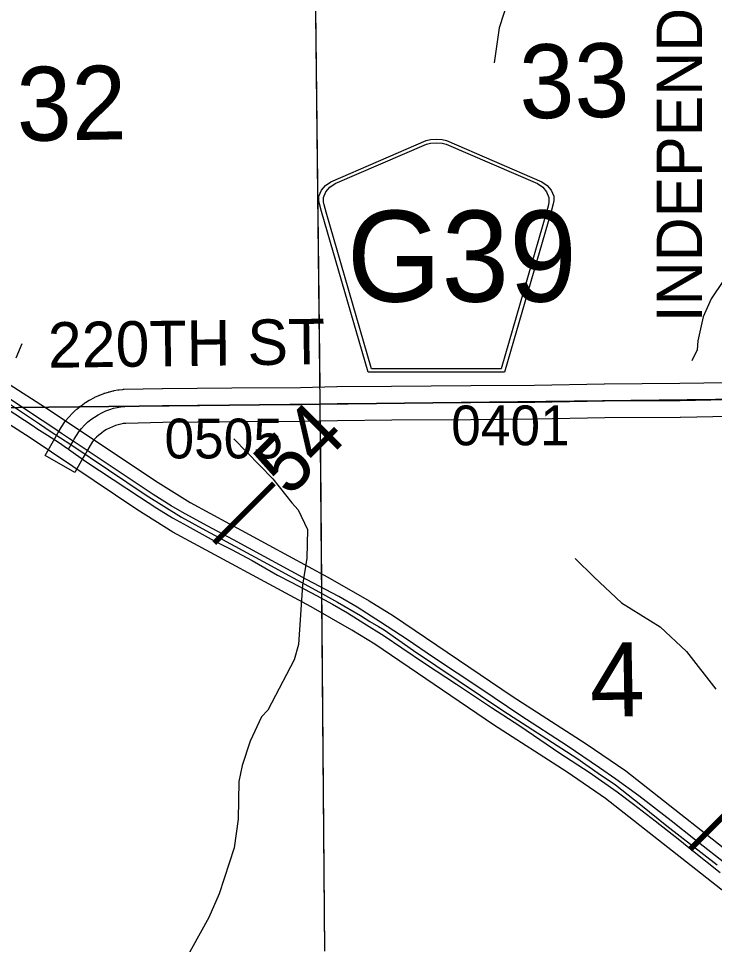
# Model space of a CAD drawing. Extents: x 23.6 to 68.7, y -63 to -29.
# Drawn here: x 40.131 to 41.355, y -46.611 to -44.982 of the extents above; entities that cross this region are included whole.
import ezdxf

# ---------------------------------------------------------------- set-up
doc = ezdxf.new("R2010")
doc.units = 0
for name, color, linetype in [('tdCoDivCarto', 7, 'Continuous'), ('tdCoHydroRiver', 7, 'Continuous'), ('tdCoPriCL', 7, 'Continuous'), ('tdCoPriDiv', 7, 'Continuous'), ('tdCoPrimary', 7, 'Continuous'), ('tdCoSecRdNmbr', 7, 'Continuous'), ('tdCoSecRdTxt', 7, 'Continuous'), ('tdCoSecRteBand', 7, 'Continuous'), ('tdCoSecRteCL', 7, 'Continuous'), ('tdCoSectLine', 7, 'Continuous'), ('tdCoSectLinePart', 7, 'Continuous'), ('tdCoSectNmbr', 7, 'Continuous'), ('tdCoShieldCoRte', 7, 'Continuous'), ('tdCoSurfGravel', 7, 'Continuous'), ('tdCoTwpBndryShd', 7, 'Continuous'), ('tdStHwyPriRefPost1', 7, 'Continuous'), ('tdStHwyPriRefPost5', 7, 'Continuous')]:
    doc.layers.add(name, color=color, linetype=linetype)

msp = doc.modelspace()

# ---------------------------------------------------------------- linework, layer by layer
at = {"layer": 'tdCoDivCarto'}
for p, q in [((40.1725, -45.6894), (40.1031, -45.643)), ((40.1096, -45.6677), (40.1569, -45.699)), ((40.1911, -45.7019), (40.1725, -45.6894)), ((40.1911, -45.7019), (40.1725, -45.6894)), ((40.1569, -45.699), (40.1635, -45.7032)), ((40.1635, -45.7032), (40.1823, -45.7154)), ((40.1635, -45.7032), (40.1823, -45.7154)), ((40.2064, -45.7121), (40.1911, -45.7019)), ((40.2208, -45.7216), (40.2064, -45.7121)), ((40.1823, -45.7154), (40.2013, -45.7276)), ((40.2013, -45.7276), (40.2169, -45.7385)), ((40.2269, -45.7256), (40.2208, -45.7216)), ((40.2273, -45.7259), (40.2269, -45.7256)), ((40.271, -45.7552), (40.2273, -45.7259)), ((40.2169, -45.7385), (40.2181, -45.7393)), ((40.2181, -45.7393), (40.2188, -45.7398)), ((40.2188, -45.7398), (40.2496, -45.7614)), ((40.2496, -45.7614), (40.2977, -45.7929)), ((40.329, -45.7939), (40.271, -45.7552)), ((40.2977, -45.7929), (40.3436, -45.8238)), ((40.3677, -45.8196), (40.329, -45.7939)), ((40.3436, -45.8238), (40.3744, -45.8435)), ((40.3995, -45.8393), (40.3677, -45.8196)), ((40.3744, -45.8435), (40.4018, -45.8608)), ((40.4187, -45.8507), (40.3995, -45.8393)), ((40.4018, -45.8608), (40.4277, -45.8748)), ((40.4626, -45.8746), (40.4187, -45.8507)), ((40.4277, -45.8748), (40.4753, -45.9007)), ((40.509, -45.899), (40.4626, -45.8746)), ((40.4753, -45.9007), (40.5056, -45.916)), ((40.5627, -45.9283), (40.509, -45.899)), ((40.5056, -45.916), (40.5419, -45.9355)), ((40.5419, -45.9355), (40.5865, -45.9611)), ((40.6375, -45.969), (40.5627, -45.9283)), ((40.5865, -45.9611), (40.6116, -45.9744)), ((40.6116, -45.9744), (40.655, -45.9974)), ((40.6944, -45.9991), (40.6375, -45.969)), ((40.655, -45.9974), (40.6832, -46.0124)), ((40.7262, -46.0176), (40.6944, -45.9991)), ((40.6832, -46.0124), (40.7095, -46.0277)), ((40.7672, -46.044), (40.7262, -46.0176)), ((40.7095, -46.0277), (40.7384, -46.0457)), ((40.7384, -46.0457), (40.7739, -46.0681)), ((40.8145, -46.0748), (40.7672, -46.044)), ((40.7739, -46.0681), (40.805, -46.0889)), ((40.805, -46.0889), (40.8464, -46.1175)), ((40.8609, -46.1064), (40.8145, -46.0748)), ((40.8464, -46.1175), (40.9012, -46.1532)), ((40.944, -46.1614), (40.8609, -46.1064)), ((40.9012, -46.1532), (40.9362, -46.1767)), ((41.0143, -46.2087), (40.944, -46.1614)), ((40.9362, -46.1767), (40.9623, -46.1939)), ((40.9623, -46.1939), (41.0124, -46.2262)), ((41.0954, -46.2617), (41.0143, -46.2087)), ((41.0124, -46.2262), (41.0829, -46.2743)), ((41.1524, -46.3005), (41.0954, -46.2617)), ((41.0829, -46.2743), (41.1342, -46.3079)), ((41.1812, -46.3204), (41.1524, -46.3005)), ((41.1342, -46.3079), (41.1835, -46.3426)), ((41.2217, -46.3495), (41.1812, -46.3204)), ((41.1835, -46.3426), (41.2124, -46.3641)), ((41.2786, -46.3937), (41.2217, -46.3495)), ((41.2124, -46.3641), (41.2501, -46.3932)), ((41.2501, -46.3932), (41.2938, -46.4277)), ((41.3213, -46.4277), (41.2786, -46.3937)), ((41.2938, -46.4277), (41.3162, -46.4457)), ((41.3783, -46.4721), (41.3213, -46.4277)), ((41.3162, -46.4457), (41.3645, -46.4842))]:
    msp.add_line(p, q, dxfattribs=at)
for points in [[(40.1725, -45.6894), (40.1031, -45.643), (40.0974, -45.6391)], [(40.1725, -45.6894), (40.1031, -45.643), (40.0974, -45.6391)], [(40.1725, -45.6894), (40.1031, -45.643), (40.0974, -45.6391)], [(40.0878, -45.6534), (40.1096, -45.6677), (40.1569, -45.699), (40.1635, -45.7032)], [(40.0878, -45.6534), (40.1096, -45.6677), (40.1569, -45.699), (40.1635, -45.7032)], [(40.0878, -45.6534), (40.1096, -45.6677), (40.1569, -45.699), (40.1635, -45.7032)], [(40.1911, -45.7019), (40.1725, -45.6894)], [(40.1911, -45.7019), (40.1725, -45.6894)], [(40.1635, -45.7032), (40.1823, -45.7154)], [(40.1635, -45.7032), (40.1823, -45.7154)], [(40.2273, -45.7259), (40.2269, -45.7256), (40.2208, -45.7216), (40.2064, -45.7121), (40.1911, -45.7019)], [(40.2273, -45.7259), (40.2269, -45.7256), (40.2208, -45.7216), (40.2064, -45.7121), (40.1911, -45.7019)], [(40.2273, -45.7259), (40.2269, -45.7256), (40.2208, -45.7216), (40.2064, -45.7121), (40.1911, -45.7019)], [(40.1823, -45.7154), (40.2013, -45.7276), (40.2169, -45.7385), (40.2181, -45.7393)], [(40.1823, -45.7154), (40.2013, -45.7276), (40.2169, -45.7385), (40.2181, -45.7393)], [(40.1823, -45.7154), (40.2013, -45.7276), (40.2169, -45.7385), (40.2181, -45.7393)], [(41.3783, -46.4721), (41.3213, -46.4277), (41.2786, -46.3937), (41.2217, -46.3495), (41.1812, -46.3204), (41.1524, -46.3005), (41.0954, -46.2617), (41.0143, -46.2087), (40.944, -46.1614), (40.8609, -46.1064), (40.8145, -46.0748), (40.7672, -46.044), (40.7262, -46.0176), (40.6944, -45.9991), (40.6375, -45.969), (40.5627, -45.9283), (40.509, -45.899), (40.4626, -45.8746), (40.4187, -45.8507), (40.3995, -45.8393), (40.3677, -45.8196), (40.329, -45.7939), (40.271, -45.7552), (40.2273, -45.7259)], [(41.3783, -46.4721), (41.3213, -46.4277), (41.2786, -46.3937), (41.2217, -46.3495), (41.1812, -46.3204), (41.1524, -46.3005), (41.0954, -46.2617), (41.0143, -46.2087), (40.944, -46.1614), (40.8609, -46.1064), (40.8145, -46.0748), (40.7672, -46.044), (40.7262, -46.0176), (40.6944, -45.9991), (40.6375, -45.969), (40.5627, -45.9283), (40.509, -45.899), (40.4626, -45.8746), (40.4187, -45.8507), (40.3995, -45.8393), (40.3677, -45.8196), (40.329, -45.7939), (40.271, -45.7552), (40.2273, -45.7259)], [(41.3783, -46.4721), (41.3213, -46.4277), (41.2786, -46.3937), (41.2217, -46.3495), (41.1812, -46.3204), (41.1524, -46.3005), (41.0954, -46.2617), (41.0143, -46.2087), (40.944, -46.1614), (40.8609, -46.1064), (40.8145, -46.0748), (40.7672, -46.044), (40.7262, -46.0176), (40.6944, -45.9991), (40.6375, -45.969), (40.5627, -45.9283), (40.509, -45.899), (40.4626, -45.8746), (40.4187, -45.8507), (40.3995, -45.8393), (40.3677, -45.8196), (40.329, -45.7939), (40.271, -45.7552), (40.2273, -45.7259)], [(40.2181, -45.7393), (40.2188, -45.7398), (40.2496, -45.7614), (40.2977, -45.7929), (40.3436, -45.8238), (40.3744, -45.8435), (40.4018, -45.8608), (40.4277, -45.8748), (40.4753, -45.9007), (40.5056, -45.916), (40.5419, -45.9355), (40.5865, -45.9611), (40.6116, -45.9744), (40.655, -45.9974), (40.6832, -46.0124), (40.7095, -46.0277), (40.7384, -46.0457), (40.7739, -46.0681), (40.805, -46.0889), (40.8464, -46.1175), (40.9012, -46.1532), (40.9362, -46.1767), (40.9623, -46.1939), (41.0124, -46.2262), (41.0829, -46.2743), (41.1342, -46.3079), (41.1835, -46.3426), (41.2124, -46.3641), (41.2501, -46.3932), (41.2938, -46.4277), (41.3162, -46.4457), (41.3645, -46.4842)], [(40.2181, -45.7393), (40.2188, -45.7398), (40.2496, -45.7614), (40.2977, -45.7929), (40.3436, -45.8238), (40.3744, -45.8435), (40.4018, -45.8608), (40.4277, -45.8748), (40.4753, -45.9007), (40.5056, -45.916), (40.5419, -45.9355), (40.5865, -45.9611), (40.6116, -45.9744), (40.655, -45.9974), (40.6832, -46.0124), (40.7095, -46.0277), (40.7384, -46.0457), (40.7739, -46.0681), (40.805, -46.0889), (40.8464, -46.1175), (40.9012, -46.1532), (40.9362, -46.1767), (40.9623, -46.1939), (41.0124, -46.2262), (41.0829, -46.2743), (41.1342, -46.3079), (41.1835, -46.3426), (41.2124, -46.3641), (41.2501, -46.3932), (41.2938, -46.4277), (41.3162, -46.4457), (41.3645, -46.4842)], [(40.2181, -45.7393), (40.2188, -45.7398), (40.2496, -45.7614), (40.2977, -45.7929), (40.3436, -45.8238), (40.3744, -45.8435), (40.4018, -45.8608), (40.4277, -45.8748), (40.4753, -45.9007), (40.5056, -45.916), (40.5419, -45.9355), (40.5865, -45.9611), (40.6116, -45.9744), (40.655, -45.9974), (40.6832, -46.0124), (40.7095, -46.0277), (40.7384, -46.0457), (40.7739, -46.0681), (40.805, -46.0889), (40.8464, -46.1175), (40.9012, -46.1532), (40.9362, -46.1767), (40.9623, -46.1939), (41.0124, -46.2262), (41.0829, -46.2743), (41.1342, -46.3079), (41.1835, -46.3426), (41.2124, -46.3641), (41.2501, -46.3932), (41.2938, -46.4277), (41.3162, -46.4457), (41.3645, -46.4842)]]:
    msp.add_lwpolyline(points, dxfattribs=at)
at = {"layer": 'tdCoHydroRiver'}
for points in [[(41.3635, -44.5499), (41.3511, -44.5769), (41.3371, -44.5928), (41.3309, -44.6055), (41.2807, -44.6438), (41.2072, -44.7156), (41.0929, -44.8114), (41.0397, -44.8671), (41.0195, -44.8942), (40.9916, -44.9497), (40.9763, -44.9987), (40.9674, -45.0604)], [(41.3704, -45.4433), (41.3486, -45.4751), (41.3347, -45.5068), (41.3256, -45.5495), (41.3242, -45.5653), (41.3149, -45.5843)], [(40.137, -45.5545), (40.1262, -45.5798)], [(40.5096, -45.7214), (40.5781, -45.7918), (40.6117, -45.8341), (40.6228, -45.8466), (40.6389, -45.8812), (40.6378, -45.9317), (40.6304, -45.9791), (40.6235, -46.0834), (40.6158, -46.1103), (40.5693, -46.1991), (40.5584, -46.2103), (40.5383, -46.2531), (40.5245, -46.2959), (40.5184, -46.3243), (40.5175, -46.3906), (40.5101, -46.4412), (40.484, -46.522), (40.4654, -46.5632), (40.4018, -46.679)], [(41.1098, -45.932), (41.1433, -45.9648), (41.1911, -46.0101), (41.2593, -46.0521), (41.3055, -46.0959), (41.3567, -46.1617)]]:
    msp.add_lwpolyline(points, dxfattribs=at)
at = {"layer": 'tdCoPriCL'}
msp.add_lwpolyline([(40.1172, -45.6613), (40.1682, -45.6953), (40.1866, -45.7082), (40.223, -45.7318), (40.3556, -45.8208), (40.4176, -45.8596), (40.4542, -45.8793), (40.5611, -45.9374), (40.6603, -45.991), (40.6917, -46.0087), (40.7323, -46.0324), (40.7486, -46.0426), (40.7639, -46.0516), (40.774, -46.0578), (40.8253, -46.0939), (40.9826, -46.1994), (41.1125, -46.2831), (41.1503, -46.3096), (41.1807, -46.3299), (41.2252, -46.3655), (41.2709, -46.4021), (41.3594, -46.4707)], dxfattribs=at)
at = {"layer": 'tdCoPriDiv'}
for points in [[(41.3902, -46.5327), (41.163, -46.3542), (41.0958, -46.308), (40.9662, -46.2244), (40.7576, -46.0829), (40.7169, -46.0581), (40.6458, -46.0172), (40.4026, -45.8856), (40.3393, -45.846), (40.1513, -45.7201), (40.0759, -45.672), (40.0211, -45.6356), (39.9494, -45.5847), (39.7956, -45.4821), (39.6357, -45.3738), (39.039, -44.9752), (38.811, -44.8202), (38.7533, -44.7818), (38.6853, -44.7238), (38.6486, -44.6876), (38.6183, -44.6558), (38.5702, -44.6089), (38.5405, -44.5829), (38.379, -44.4338)], [(39.0725, -44.9254), (39.6693, -45.3242), (39.8281, -45.4316), (39.9836, -45.5354), (40.0549, -45.586), (40.1079, -45.6213), (40.1852, -45.6705), (40.3719, -45.7956), (40.4328, -45.8336), (40.6749, -45.9647), (40.7478, -46.0067), (40.7905, -46.0327), (40.9991, -46.1743), (41.1293, -46.2582), (41.1985, -46.3057), (41.4276, -46.4858)]]:
    msp.add_lwpolyline(points, dxfattribs=at)
at = {"layer": 'tdCoPrimary'}
for p, q in [((40.1911, -45.7019), (40.1725, -45.6894)), ((40.1911, -45.7019), (40.1725, -45.6894)), ((40.1635, -45.7032), (40.1823, -45.7154)), ((40.1635, -45.7032), (40.1823, -45.7154))]:
    msp.add_line(p, q, dxfattribs=at)
for points in [[(40.1725, -45.6894), (40.1031, -45.643), (40.0974, -45.6391)], [(40.1725, -45.6894), (40.1031, -45.643), (40.0974, -45.6391)], [(41.3783, -46.4721), (41.3213, -46.4277), (41.2786, -46.3937), (41.2217, -46.3495), (41.1812, -46.3204), (41.1524, -46.3005), (41.0954, -46.2617), (41.0143, -46.2087), (40.944, -46.1614), (40.8609, -46.1064), (40.8145, -46.0748), (40.7672, -46.044), (40.7262, -46.0176), (40.6944, -45.9991), (40.6375, -45.969), (40.5627, -45.9283), (40.509, -45.899), (40.4626, -45.8746), (40.4187, -45.8507), (40.3995, -45.8393), (40.3677, -45.8196), (40.329, -45.7939), (40.271, -45.7552), (40.2273, -45.7259), (40.2269, -45.7256), (40.2208, -45.7216), (40.2064, -45.7121), (40.1911, -45.7019), (40.1725, -45.6894), (40.1031, -45.643)], [(40.0878, -45.6534), (40.1096, -45.6677), (40.1569, -45.699), (40.1635, -45.7032)], [(40.0878, -45.6534), (40.1096, -45.6677), (40.1569, -45.699), (40.1635, -45.7032)], [(40.1096, -45.6677), (40.1569, -45.699), (40.1635, -45.7032), (40.1823, -45.7154), (40.2013, -45.7276), (40.2169, -45.7385), (40.2181, -45.7393), (40.2188, -45.7398), (40.2496, -45.7614), (40.2977, -45.7929), (40.3436, -45.8238), (40.3744, -45.8435), (40.4018, -45.8608), (40.4277, -45.8748), (40.4753, -45.9007), (40.5056, -45.916), (40.5419, -45.9355), (40.5865, -45.9611), (40.6116, -45.9744), (40.655, -45.9974), (40.6832, -46.0124), (40.7095, -46.0277), (40.7384, -46.0457), (40.7739, -46.0681), (40.805, -46.0889), (40.8464, -46.1175), (40.9012, -46.1532), (40.9362, -46.1767), (40.9623, -46.1939), (41.0124, -46.2262), (41.0829, -46.2743), (41.1342, -46.3079), (41.1835, -46.3426), (41.2124, -46.3641), (41.2501, -46.3932), (41.2938, -46.4277), (41.3162, -46.4457), (41.3645, -46.4842)], [(40.2273, -45.7259), (40.2269, -45.7256), (40.2208, -45.7216), (40.2064, -45.7121), (40.1911, -45.7019)], [(40.2273, -45.7259), (40.2269, -45.7256), (40.2208, -45.7216), (40.2064, -45.7121), (40.1911, -45.7019)], [(40.1823, -45.7154), (40.2013, -45.7276), (40.2169, -45.7385), (40.2181, -45.7393)], [(40.1823, -45.7154), (40.2013, -45.7276), (40.2169, -45.7385), (40.2181, -45.7393)], [(41.3783, -46.4721), (41.3213, -46.4277), (41.2786, -46.3937), (41.2217, -46.3495), (41.1812, -46.3204), (41.1524, -46.3005), (41.0954, -46.2617), (41.0143, -46.2087), (40.944, -46.1614), (40.8609, -46.1064), (40.8145, -46.0748), (40.7672, -46.044), (40.7262, -46.0176), (40.6944, -45.9991), (40.6375, -45.969), (40.5627, -45.9283), (40.509, -45.899), (40.4626, -45.8746), (40.4187, -45.8507), (40.3995, -45.8393), (40.3677, -45.8196), (40.329, -45.7939), (40.271, -45.7552), (40.2273, -45.7259)], [(41.3783, -46.4721), (41.3213, -46.4277), (41.2786, -46.3937), (41.2217, -46.3495), (41.1812, -46.3204), (41.1524, -46.3005), (41.0954, -46.2617), (41.0143, -46.2087), (40.944, -46.1614), (40.8609, -46.1064), (40.8145, -46.0748), (40.7672, -46.044), (40.7262, -46.0176), (40.6944, -45.9991), (40.6375, -45.969), (40.5627, -45.9283), (40.509, -45.899), (40.4626, -45.8746), (40.4187, -45.8507), (40.3995, -45.8393), (40.3677, -45.8196), (40.329, -45.7939), (40.271, -45.7552), (40.2273, -45.7259)], [(40.2181, -45.7393), (40.2188, -45.7398), (40.2496, -45.7614), (40.2977, -45.7929), (40.3436, -45.8238), (40.3744, -45.8435), (40.4018, -45.8608), (40.4277, -45.8748), (40.4753, -45.9007), (40.5056, -45.916), (40.5419, -45.9355), (40.5865, -45.9611), (40.6116, -45.9744), (40.655, -45.9974), (40.6832, -46.0124), (40.7095, -46.0277), (40.7384, -46.0457), (40.7739, -46.0681), (40.805, -46.0889), (40.8464, -46.1175), (40.9012, -46.1532), (40.9362, -46.1767), (40.9623, -46.1939), (41.0124, -46.2262), (41.0829, -46.2743), (41.1342, -46.3079), (41.1835, -46.3426), (41.2124, -46.3641), (41.2501, -46.3932), (41.2938, -46.4277), (41.3162, -46.4457), (41.3645, -46.4842)], [(40.2181, -45.7393), (40.2188, -45.7398), (40.2496, -45.7614), (40.2977, -45.7929), (40.3436, -45.8238), (40.3744, -45.8435), (40.4018, -45.8608), (40.4277, -45.8748), (40.4753, -45.9007), (40.5056, -45.916), (40.5419, -45.9355), (40.5865, -45.9611), (40.6116, -45.9744), (40.655, -45.9974), (40.6832, -46.0124), (40.7095, -46.0277), (40.7384, -46.0457), (40.7739, -46.0681), (40.805, -46.0889), (40.8464, -46.1175), (40.9012, -46.1532), (40.9362, -46.1767), (40.9623, -46.1939), (41.0124, -46.2262), (41.0829, -46.2743), (41.1342, -46.3079), (41.1835, -46.3426), (41.2124, -46.3641), (41.2501, -46.3932), (41.2938, -46.4277), (41.3162, -46.4457), (41.3645, -46.4842)]]:
    msp.add_lwpolyline(points, dxfattribs=at)
at = {"layer": 'tdCoSecRteBand'}
msp.add_lwpolyline([(41.3802, -45.6824), (41.2946, -45.6839), (41.2944, -45.6839), (41.2942, -45.6839), (41.1616, -45.6846), (41.0393, -45.6872), (41.039, -45.6872), (41.0388, -45.6872), (40.9265, -45.6879), (40.7875, -45.6889), (40.692, -45.6897), (40.6278, -45.6912), (40.6275, -45.6912), (40.6273, -45.6912), (40.5066, -45.6918), (40.3849, -45.6928), (40.3197, -45.6944), (40.3153, -45.6949), (40.3107, -45.6957), (40.3061, -45.6968), (40.3015, -45.6983), (40.2961, -45.7003), (40.291, -45.7026), (40.286, -45.7053), (40.2812, -45.7082), (40.2767, -45.7115), (40.2723, -45.7151), (40.2682, -45.7189), (40.2643, -45.723), (40.2614, -45.7265), (40.2546, -45.7377), (40.253, -45.7405), (40.2494, -45.7466), (40.2449, -45.7547), (40.23, -45.7807), (40.1779, -45.751), (40.1927, -45.725), (40.1973, -45.7169), (40.2008, -45.7107), (40.2027, -45.7075), (40.2029, -45.707), (40.2032, -45.7066), (40.2114, -45.6933), (40.2125, -45.6915), (40.2138, -45.6899), (40.2187, -45.6841), (40.2193, -45.6833), (40.22, -45.6826), (40.2252, -45.6771), (40.2258, -45.6764), (40.2265, -45.6757), (40.2321, -45.6705), (40.2328, -45.6699), (40.2336, -45.6693), (40.2394, -45.6645), (40.2402, -45.6638), (40.241, -45.6633), (40.2471, -45.6589), (40.2479, -45.6583), (40.2488, -45.6578), (40.2552, -45.6538), (40.256, -45.6533), (40.2569, -45.6528), (40.2636, -45.6492), (40.2644, -45.6488), (40.2653, -45.6484), (40.2722, -45.6452), (40.2731, -45.6448), (40.274, -45.6445), (40.2811, -45.6418), (40.2819, -45.6415), (40.2827, -45.6413), (40.2891, -45.6393), (40.29, -45.639), (40.291, -45.6388), (40.2974, -45.6372), (40.2984, -45.637), (40.2994, -45.6368), (40.3059, -45.6356), (40.3069, -45.6355), (40.3078, -45.6354), (40.3145, -45.6346), (40.3157, -45.6345), (40.317, -45.6345), (40.3837, -45.6328), (40.384, -45.6328), (40.3842, -45.6328), (40.5062, -45.6318), (40.5062, -45.6318), (40.5063, -45.6318), (40.6267, -45.6312), (40.6909, -45.6297), (40.6911, -45.6297), (40.6913, -45.6297), (40.787, -45.6289), (40.787, -45.6289), (40.787, -45.6289), (40.9261, -45.6279), (40.9261, -45.6279), (40.9261, -45.6279), (41.0382, -45.6272), (41.1606, -45.6246), (41.1609, -45.6246), (41.1611, -45.6246), (41.2937, -45.6239), (41.3783, -45.6224)], dxfattribs=at)
at = {"layer": 'tdCoSecRteCL'}
msp.add_lwpolyline([(40.2188, -45.7398), (40.2234, -45.7318), (40.2269, -45.7256), (40.2288, -45.7223), (40.237, -45.709), (40.2418, -45.7032), (40.247, -45.6977), (40.2525, -45.6925), (40.2584, -45.6877), (40.2646, -45.6833), (40.271, -45.6793), (40.2777, -45.6757), (40.2846, -45.6726), (40.2917, -45.6699), (40.2981, -45.6679), (40.3045, -45.6663), (40.3111, -45.6652), (40.3177, -45.6645), (40.3844, -45.6628), (40.5064, -45.6618), (40.6271, -45.6612), (40.6915, -45.6597), (40.7872, -45.6589), (40.9263, -45.6579), (41.0386, -45.6572), (41.1613, -45.6546), (41.2941, -45.6539), (41.4024, -45.652)], dxfattribs=at)
at = {"layer": 'tdCoSectLine'}
for points in [[(40.6495, -44.6571), (40.661, -45.6604)], [(40.661, -45.6604), (41.6548, -45.649)], [(39.6539, -45.6718), (40.661, -45.6604)], [(40.661, -45.6604), (40.6692, -46.6228)]]:
    msp.add_lwpolyline(points, dxfattribs=at)
at = {"layer": 'tdCoSectLinePart'}
for points in [[(40.6495, -44.6571), (40.6607, -45.6305)], [(40.0172, -45.6677), (40.2386, -45.6652)], [(40.6613, -45.6904), (40.6692, -46.6228)]]:
    msp.add_lwpolyline(points, dxfattribs=at)
at = {"layer": 'tdCoShieldCoRte'}
for points in [[(40.7458, -45.6045), (40.6638, -45.3217), (40.66, -45.3085), (40.6592, -45.3026), (40.6592, -45.2948), (40.6635, -45.2845), (40.6708, -45.276), (40.6803, -45.2693), (40.8476, -45.197), (40.8551, -45.1953), (40.8655, -45.1944), (40.876, -45.1953), (40.8835, -45.197), (41.0508, -45.2693), (41.0603, -45.276), (41.0676, -45.2845), (41.0719, -45.2948), (41.0719, -45.3026), (41.0711, -45.3085), (41.0673, -45.3217), (40.9853, -45.6045)], [(40.7516, -45.5982), (40.6719, -45.3229), (40.6682, -45.3103), (40.6675, -45.3047), (40.6675, -45.2972), (40.6716, -45.2873), (40.6785, -45.2791), (40.6877, -45.2727), (40.8483, -45.2033), (40.8555, -45.2017), (40.8655, -45.2008), (40.8756, -45.2017), (40.8828, -45.2033), (41.0434, -45.2727), (41.0526, -45.2791), (41.0595, -45.2873), (41.0636, -45.2972), (41.0636, -45.3047), (41.0629, -45.3103), (41.0592, -45.3229), (40.9794, -45.5982)]]:
    msp.add_lwpolyline(points, close=True, dxfattribs=at)
at = {"layer": 'tdCoSurfGravel'}
msp.add_line((40.2188, -45.7398), (40.2234, -45.7318), dxfattribs=at)
msp.add_lwpolyline([(40.2234, -45.7318), (40.2269, -45.7256), (40.2288, -45.7223), (40.237, -45.709), (40.2418, -45.7032), (40.247, -45.6977), (40.2525, -45.6925), (40.2584, -45.6877), (40.2646, -45.6833), (40.271, -45.6793), (40.2777, -45.6757), (40.2846, -45.6726), (40.2917, -45.6699), (40.2981, -45.6679), (40.3045, -45.6663), (40.3111, -45.6652), (40.3177, -45.6645), (40.3844, -45.6628), (40.5064, -45.6618), (40.6271, -45.6612), (40.6915, -45.6597), (40.7872, -45.6589), (40.9263, -45.6579), (41.0386, -45.6572), (41.1613, -45.6546), (41.2941, -45.6539), (41.4024, -45.652)], dxfattribs=at)
at = {"layer": 'tdCoTwpBndryShd'}
msp.add_lwpolyline([(44.659, -45.6063), (43.6569, -45.6219), (42.6564, -45.6349), (41.6548, -45.649), (40.661, -45.6604), (39.6539, -45.6718), (38.6948, -45.6802), (37.6909, -45.6918), (36.7012, -45.7036), (36.6871, -45.7039), (35.6948, -45.7141), (35.6828, -45.7143), (34.6942, -45.7256), (34.6845, -45.726), (33.6895, -45.7373), (33.6806, -45.7374), (32.7232, -45.7449)], dxfattribs=at)

# ---------------------------------------------------------------- texts
at = {"layer": 'tdCoSecRdNmbr'}
for s, rotation, p in [('0401', 0.032, (40.8918, -45.733)), ('0505', 0.0316, (40.3877, -45.7561))]:
    msp.add_text(s, height=0.07, rotation=rotation, dxfattribs=at).set_placement(p)
at = {"layer": 'tdCoSecRdTxt'}
for s, rotation, p in [('INDEPENDENCE', 90, (41.3328, -45.5164)), ('220TH ST', 0.7642, (40.1832, -45.5967))]:
    msp.add_text(s, height=0.08, rotation=rotation, dxfattribs=at).set_placement(p)
at = {"layer": 'tdCoSectNmbr'}
for s, rotation, p in [('33', 1.0321, (41.0124, -45.1584)), ('32', 1.0314, (40.1287, -45.198)), ('4', 1.0321, (41.1363, -46.2108))]:
    msp.add_text(s, height=0.13, rotation=rotation, dxfattribs=at).set_placement(p)
at = {"layer": 'tdCoShieldCoRte'}
msp.add_text('G39', height=0.16, dxfattribs=at).set_placement((40.7082, -45.4803))
at = {"layer": 'tdStHwyPriRefPost1'}
for s, p in [('‒‒54', (40.5012, -45.9311)), ('‒‒55', (41.3375, -46.4701))]:
    msp.add_text(s, height=0.1, rotation=45, dxfattribs=at).set_placement(p)
at = {"layer": 'tdStHwyPriRefPost5'}
msp.add_text('‒‒55', height=0.1, rotation=45, dxfattribs=at).set_placement((41.3375, -46.4701))

doc.saveas('drawing.dxf')
